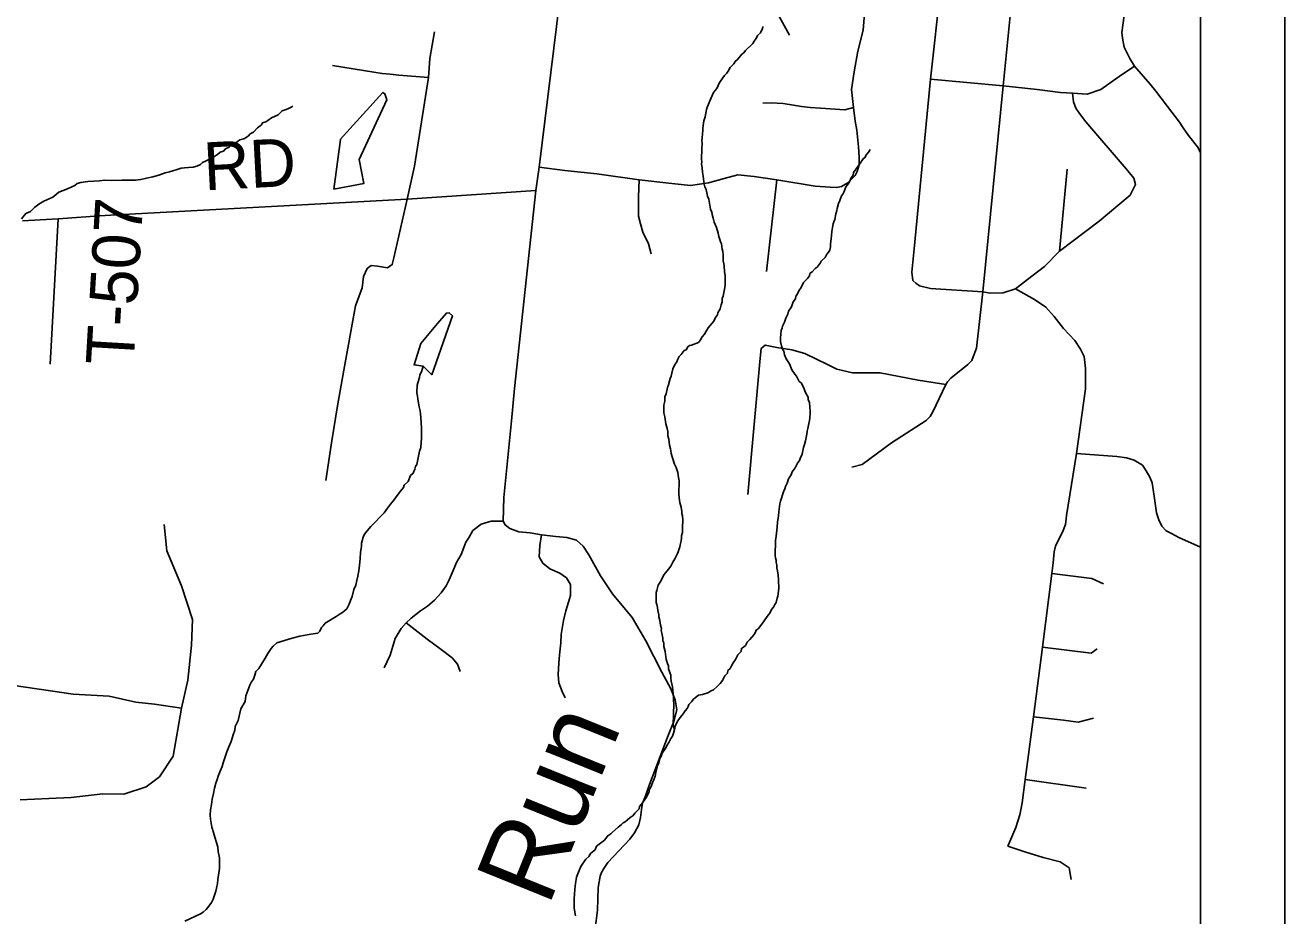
# Model space of a CAD drawing. Extents: x 44.2 to 78.2, y 4.5 to 26.5.
# Drawn here: x 51.74 to 53.236, y 20.407 to 21.465 of the extents above; entities that cross this region are included whole.
import ezdxf

# ---------------------------------------------------------------- set-up
doc = ezdxf.new("R2010")
doc.units = 0
for name, color, linetype in [('GM_X_County_Road', 7, 'Continuous'), ('GM_X_Minor_Lake', 7, 'Continuous'), ('GM_X_Minor_River', 7, 'Continuous'), ('GM_X_Minor_River_Text', 7, 'Continuous'), ('GM_X_Rail_Line', 7, 'Continuous'), ('GM_X_Township_Road', 7, 'Continuous'), ('GM_X_Township_Road_Text', 7, 'Continuous'), ('SH_Cut_Line', 7, 'Continuous'), ('SH_Data', 7, 'Continuous')]:
    doc.layers.add(name, color=color, linetype=linetype)

msp = doc.modelspace()

# ---------------------------------------------------------------- linework, layer by layer
at = {"layer": 'GM_X_County_Road'}
msp.add_lwpolyline([(52.4171, 20.3916), (52.4198, 20.4137), (52.4207, 20.4404), (52.4229, 20.454), (52.4245, 20.4585), (52.4273, 20.4633), (52.432, 20.4704), (52.4582, 20.498), (52.4639, 20.5053), (52.4691, 20.5151), (52.4711, 20.5235), (52.472, 20.5332), (52.4735, 20.5407), (52.4763, 20.5481), (52.4817, 20.5627), (52.5039, 20.621), (52.5106, 20.6377), (52.514, 20.6516), (52.5119, 20.6635), (52.507, 20.6764), (52.4963, 20.6964), (52.4771, 20.7336), (52.4612, 20.7614), (52.4377, 20.7893), (52.4236, 20.8106), (52.4096, 20.8355), (52.4027, 20.8461), (52.3948, 20.8532), (52.3835, 20.8561), (52.3704, 20.8575), (52.3532, 20.8594), (52.34, 20.8616), (52.3266, 20.8631), (52.3159, 20.8668), (52.3104, 20.8711), (52.3079, 20.8757), (52.3085, 20.9039), (52.3176, 20.9946), (52.3212, 21.0331), (52.3467, 21.2684), (52.3505, 21.2962), (52.3746, 21.4919)], dxfattribs=at)
at = {"layer": 'GM_X_Minor_Lake'}
for points in [[(52.1067, 21.2699), (52.1425, 21.2768), (52.137, 21.305), (52.1696, 21.376), (52.1675, 21.3833), (52.1652, 21.3848), (52.1144, 21.3289)], [(52.1146, 21.3291), (52.1067, 21.2699)], [(52.213, 21.0598), (52.2231, 21.0495), (52.2477, 21.1196), (52.2439, 21.1231), (52.2405, 21.1228), (52.23, 21.1105)], [(52.23, 21.1105), (52.2102, 21.0866), (52.2021, 21.0613), (52.213, 21.0598)]]:
    msp.add_lwpolyline(points, dxfattribs=at)
at = {"layer": 'GM_X_Minor_River'}
for points in [[(52.5227, 21.0782), (52.525, 21.0793), (52.527, 21.0827), (52.5293, 21.0841), (52.5316, 21.0848), (52.5396, 21.088), (52.542, 21.091), (52.544, 21.0944), (52.5471, 21.0977), (52.5511, 21.1052), (52.5535, 21.1082), (52.5558, 21.1104), (52.5581, 21.113), (52.5601, 21.1175), (52.5625, 21.1208), (52.5629, 21.1231), (52.5654, 21.128), (52.5666, 21.1325), (52.5678, 21.1362), (52.5679, 21.14), (52.5691, 21.1427), (52.5701, 21.1491), (52.5709, 21.1532), (52.5714, 21.1559), (52.5716, 21.1631), (52.5713, 21.1673), (52.5706, 21.1718), (52.5701, 21.1791), (52.5697, 21.1813), (52.5691, 21.1848), (52.5689, 21.192), (52.5686, 21.1958), (52.5679, 21.1985), (52.5669, 21.2049), (52.5658, 21.2072), (52.5652, 21.2103), (52.5641, 21.2137), (52.5631, 21.2176), (52.5613, 21.2244), (52.5585, 21.2309), (52.5571, 21.2355), (52.556, 21.2397), (52.5557, 21.2428), (52.5539, 21.2462), (52.553, 21.2535), (52.5519, 21.2581), (52.5505, 21.2615), (52.5488, 21.2695), (52.5474, 21.2726), (52.5467, 21.276), (52.5457, 21.2821), (52.5454, 21.2855), (52.5444, 21.2901), (52.5442, 21.2954), (52.5435, 21.2996), (52.5436, 21.3023), (52.5433, 21.3057), (52.5436, 21.3178), (52.5441, 21.3243), (52.5438, 21.3281), (52.5443, 21.3303), (52.5444, 21.3364), (52.5449, 21.339), (52.545, 21.3425), (52.5459, 21.3485), (52.5463, 21.3511), (52.5476, 21.3557), (52.5493, 21.3647), (52.5506, 21.3681), (52.5538, 21.3756), (52.5574, 21.3846), (52.5614, 21.3894), (52.5633, 21.3932), (52.5642, 21.3958), (52.5661, 21.3981), (52.5705, 21.4051), (52.5736, 21.4077), (52.5752, 21.41), (52.5772, 21.4145), (52.5799, 21.4167), (52.5819, 21.4189), (52.5834, 21.4215), (52.5858, 21.4237), (52.5881, 21.4263), (52.5913, 21.4304), (52.5936, 21.4319), (52.5955, 21.4348), (52.6041, 21.443), (52.6057, 21.4459), (52.6084, 21.4489), (52.61, 21.4523), (52.6132, 21.4556), (52.6144, 21.4582), (52.6156, 21.4605), (52.616, 21.4631)], [(51.7359, 21.2346), (51.741, 21.241), (51.7467, 21.2435), (51.7518, 21.2486), (51.7565, 21.2523), (51.7626, 21.2556), (51.7734, 21.2606), (51.7804, 21.2665), (51.7907, 21.2704), (51.7957, 21.2729), (51.7992, 21.2743), (51.8023, 21.2765), (51.8065, 21.2779), (51.8149, 21.2792), (51.8221, 21.2794), (51.8286, 21.28), (51.8347, 21.2806), (51.8426, 21.2804), (51.8552, 21.2805), (51.8631, 21.2806), (51.8715, 21.2808), (51.8776, 21.2814), (51.8845, 21.2831), (51.8921, 21.2844), (51.899, 21.2865), (51.9024, 21.2876), (51.9067, 21.2894), (51.9116, 21.2907), (51.9158, 21.2918), (51.9208, 21.2935), (51.9258, 21.2949), (51.9296, 21.2952), (51.9342, 21.2955), (51.9399, 21.2961), (51.9441, 21.2971), (51.9487, 21.2993), (51.951, 21.3015), (51.9553, 21.3036), (51.9607, 21.3065), (51.9634, 21.308), (51.9688, 21.3113), (51.9719, 21.3138), (51.9757, 21.3152), (51.9784, 21.3178), (51.9827, 21.32), (51.9861, 21.3229), (51.9908, 21.3255), (51.9954, 21.3284), (52, 21.3298), (52.0027, 21.3312), (52.0054, 21.3331), (52.0077, 21.3357), (52.0116, 21.3378), (52.0163, 21.3426), (52.0209, 21.3463), (52.0221, 21.3486), (52.026, 21.35), (52.0283, 21.3514), (52.0329, 21.3547), (52.0406, 21.3583), (52.0457, 21.3631), (52.0503, 21.3645), (52.0529, 21.3656), (52.056, 21.3674), (52.0583, 21.3685)], [(52.6853, 21.1844), (52.69, 21.1888), (52.692, 21.1929), (52.6943, 21.1951), (52.6959, 21.1974), (52.6964, 21.2015), (52.6964, 21.205), (52.6974, 21.211), (52.6978, 21.2148), (52.698, 21.2197), (52.6988, 21.2246), (52.6997, 21.2288), (52.7005, 21.231), (52.7017, 21.234), (52.7027, 21.2405), (52.7039, 21.2446), (52.7043, 21.2469), (52.706, 21.2529), (52.7076, 21.2563), (52.7097, 21.2619), (52.7112, 21.2641), (52.7128, 21.2671), (52.7149, 21.2728), (52.7165, 21.275), (52.7192, 21.2787), (52.7212, 21.2836), (52.7236, 21.2866), (52.724, 21.2896), (52.7288, 21.2967), (52.7311, 21.2996), (52.7351, 21.306), (52.7374, 21.3074), (52.7394, 21.3112), (52.7421, 21.3142), (52.7434, 21.3172)], [(52.6108, 20.7478), (52.6127, 20.75), (52.6147, 20.753), (52.617, 20.7559), (52.6186, 20.7586), (52.6206, 20.7612), (52.6226, 20.7641), (52.6245, 20.7664), (52.6265, 20.7709), (52.6289, 20.7735), (52.6305, 20.7765), (52.6321, 20.7791), (52.6333, 20.784), (52.6338, 20.7866), (52.6351, 20.7957), (52.6352, 20.7995), (52.6349, 20.8018), (52.6347, 20.8059), (52.6344, 20.8116), (52.6334, 20.8166), (52.6327, 20.8204), (52.6328, 20.8234), (52.6321, 20.8265), (52.6318, 20.8292), (52.6311, 20.8318), (52.6308, 20.8349), (52.6313, 20.8527), (52.6318, 20.858), (52.6332, 20.8686), (52.6337, 20.8743), (52.6347, 20.8818), (52.6352, 20.8867), (52.6362, 20.8962), (52.637, 20.8992), (52.6407, 20.9105), (52.6423, 20.9142), (52.6432, 20.9169), (52.6452, 20.9206), (52.6468, 20.9259), (52.65, 20.9307), (52.6508, 20.9341), (52.6547, 20.939), (52.6572, 20.9446), (52.6595, 20.9476), (52.6603, 20.9502), (52.6628, 20.9554), (52.6645, 20.963), (52.6657, 20.9667), (52.6669, 20.9709), (52.6683, 20.9788), (52.6688, 20.9826), (52.6696, 20.9856), (52.6709, 20.9917), (52.6714, 20.9951), (52.6718, 20.9981), (52.6724, 21.0041), (52.6724, 21.0064), (52.6721, 21.011), (52.6715, 21.0167), (52.6701, 21.0201), (52.6698, 21.0228), (52.6673, 21.0278), (52.6662, 21.0305), (52.6644, 21.0347), (52.6615, 21.0401), (52.6593, 21.0417), (52.656, 21.0478), (52.6542, 21.0501), (52.6505, 21.0552), (52.648, 21.0624), (52.644, 21.0686), (52.6418, 21.0732), (52.6412, 21.0774), (52.6397, 21.0801), (52.6383, 21.0839), (52.6373, 21.0889), (52.637, 21.0931), (52.6375, 21.098), (52.638, 21.1022), (52.6392, 21.1048), (52.6397, 21.1074), (52.642, 21.1119), (52.6433, 21.1168), (52.6457, 21.1213), (52.6466, 21.1251), (52.6501, 21.1303), (52.6522, 21.1363), (52.6549, 21.1397), (52.6554, 21.1427), (52.6569, 21.1449), (52.6593, 21.1498), (52.6613, 21.1524), (52.6645, 21.1591), (52.6692, 21.1639), (52.6715, 21.1669), (52.672, 21.1696), (52.6747, 21.1718), (52.6782, 21.1758), (52.6805, 21.1773), (52.6841, 21.1821), (52.6853, 21.1844)], [(52.5112, 20.6278), (52.5106, 20.6305), (52.5099, 20.6339), (52.5105, 20.6586), (52.5102, 20.6628), (52.5103, 20.6665), (52.5097, 20.6704), (52.5091, 20.6787), (52.5074, 20.6856), (52.5071, 20.6894), (52.5068, 20.6928), (52.5058, 20.6959), (52.5043, 20.7001), (52.5041, 20.7039), (52.503, 20.7066), (52.5016, 20.7112), (52.5003, 20.7207), (52.4986, 20.7268), (52.4987, 20.731), (52.4976, 20.7337), (52.4973, 20.7367), (52.4963, 20.7428), (52.4956, 20.7458), (52.4957, 20.7481), (52.4947, 20.7523), (52.494, 20.7576), (52.4926, 20.7619), (52.4927, 20.7645), (52.4917, 20.7695), (52.491, 20.7729), (52.4903, 20.7767), (52.4896, 20.779), (52.4897, 20.7813), (52.4895, 20.7874), (52.4896, 20.7911), (52.4904, 20.7934), (52.4921, 20.7998), (52.4944, 20.8032), (52.4972, 20.8084), (52.4988, 20.8118), (52.5008, 20.8144), (52.5043, 20.8188), (52.5071, 20.8222), (52.5095, 20.827), (52.5118, 20.8308), (52.5134, 20.8342), (52.515, 20.8371), (52.5155, 20.8394), (52.5175, 20.8451), (52.5184, 20.8492), (52.5192, 20.8522), (52.5197, 20.856), (52.5198, 20.8583), (52.5206, 20.862), (52.5208, 20.8677), (52.5209, 20.8715), (52.5213, 20.8738), (52.521, 20.8776), (52.5207, 20.8821), (52.5201, 20.8848), (52.5201, 20.8871), (52.5191, 20.8924), (52.5177, 20.8978), (52.5174, 20.9001), (52.5165, 20.9077), (52.5169, 20.9236), (52.5162, 20.9274), (52.5152, 20.9335), (52.5142, 20.9369), (52.5131, 20.9393), (52.5113, 20.9435), (52.5088, 20.9507), (52.5074, 20.9561), (52.5071, 20.9591), (52.5064, 20.9614), (52.5054, 20.966), (52.5044, 20.9732), (52.5034, 20.9771), (52.5035, 20.982), (52.5025, 20.9858), (52.5011, 20.9912), (52.4998, 20.9995), (52.4988, 21.0041), (52.4988, 21.0064), (52.4985, 21.0094), (52.4986, 21.0136), (52.4999, 21.0181), (52.5, 21.0234), (52.5013, 21.0268), (52.503, 21.0344), (52.5042, 21.0374), (52.5063, 21.0449), (52.5075, 21.0479), (52.508, 21.0513), (52.5092, 21.0566), (52.5116, 21.0618), (52.5136, 21.0641), (52.5152, 21.0682), (52.5168, 21.0712), (52.5191, 21.0734), (52.5227, 21.0782)], [(52.2086, 20.9586), (52.2102, 20.9631), (52.2109, 20.9745), (52.211, 20.9802), (52.2108, 20.9862), (52.2106, 20.9927), (52.2097, 21.0037), (52.2091, 21.0083), (52.208, 21.0114), (52.2071, 21.0182), (52.2067, 21.0209), (52.2061, 21.0239), (52.2054, 21.0281), (52.2056, 21.0372), (52.2065, 21.0398), (52.2085, 21.0462), (52.209, 21.0496), (52.211, 21.053), (52.2122, 21.0568), (52.213, 21.0598)], [(51.9666, 20.4361), (51.9675, 20.4398), (51.9688, 20.4451), (51.9693, 20.45), (51.9711, 20.4633), (51.9713, 20.4682), (51.971, 20.4724), (51.9711, 20.4758), (51.9697, 20.4834), (51.9691, 20.4883), (51.9674, 20.4941), (51.9656, 20.5002), (51.9639, 20.5059), (51.9621, 20.5121), (51.9611, 20.517), (51.9605, 20.5216), (51.9602, 20.5265), (51.9604, 20.5326), (51.9617, 20.539), (51.9626, 20.5454), (51.9639, 20.5522), (51.9652, 20.5586), (51.9669, 20.5643), (51.9685, 20.5688), (51.9697, 20.5729), (51.9718, 20.5786), (51.9742, 20.5842), (51.9755, 20.5887), (51.9775, 20.5947), (51.98, 20.6015), (51.982, 20.6075), (51.9848, 20.6139), (51.9873, 20.6218), (51.9894, 20.6274), (51.9898, 20.6316), (51.9934, 20.6387), (51.9965, 20.6527), (52.0016, 20.6616), (52.0025, 20.6681), (52.0071, 20.6809), (52.0091, 20.685), (52.0114, 20.6879), (52.0131, 20.6928), (52.0143, 20.697), (52.0178, 20.7007), (52.021, 20.7059), (52.0253, 20.713), (52.0285, 20.7186), (52.0325, 20.7242), (52.0348, 20.7272), (52.0391, 20.7312), (52.0575, 20.7368), (52.0663, 20.7389), (52.0796, 20.7416), (52.088, 20.7428), (52.0903, 20.7451), (52.0923, 20.7492), (52.0943, 20.7514), (52.0967, 20.7544), (52.1005, 20.7569), (52.1098, 20.7624), (52.1144, 20.7657), (52.1171, 20.7671), (52.1198, 20.7697), (52.1222, 20.7716), (52.1234, 20.7738), (52.125, 20.7772), (52.1266, 20.7813), (52.1286, 20.7862), (52.1307, 20.7945), (52.1328, 20.7997), (52.134, 20.805), (52.1353, 20.8103), (52.1366, 20.8167), (52.1372, 20.8235), (52.1381, 20.8307), (52.1387, 20.839), (52.1396, 20.8455), (52.1397, 20.8496), (52.1418, 20.8568), (52.1434, 20.8602), (52.1465, 20.8642), (52.1508, 20.8691), (52.1559, 20.8746), (52.1614, 20.8802), (52.1665, 20.8857), (52.1704, 20.8909), (52.1743, 20.8958), (52.1779, 20.9006), (52.1822, 20.9062), (52.1861, 20.9114), (52.1896, 20.9155), (52.1905, 20.9185), (52.1951, 20.9229), (52.198, 20.9297), (52.2011, 20.9326), (52.2031, 20.9375), (52.2039, 20.9405), (52.2055, 20.9431), (52.2073, 20.9529), (52.2086, 20.9586)], [(52.3936, 20.4067), (52.3929, 20.4112), (52.3923, 20.4162), (52.392, 20.42), (52.3922, 20.4272), (52.3927, 20.4325), (52.3929, 20.4382), (52.3933, 20.442), (52.3938, 20.4454), (52.3947, 20.4499), (52.3951, 20.4529), (52.3964, 20.4567), (52.398, 20.4608), (52.4, 20.4653), (52.4032, 20.4702), (52.4059, 20.4743), (52.4094, 20.4772), (52.4118, 20.4813), (52.4172, 20.4853), (52.4185, 20.4895), (52.4281, 20.4968), (52.4321, 20.502), (52.4356, 20.5042), (52.4375, 20.5064), (52.4445, 20.5123), (52.4484, 20.5153), (52.4503, 20.5175), (52.4526, 20.5186), (52.4553, 20.5208), (52.4588, 20.5237), (52.4623, 20.5259), (52.4643, 20.5289), (52.4694, 20.5341), (52.4698, 20.5367), (52.4722, 20.5397), (52.4761, 20.5449), (52.4781, 20.5479), (52.4797, 20.5512), (52.4813, 20.5542), (52.4813, 20.5565), (52.4829, 20.5588), (52.4841, 20.5618), (52.4854, 20.5659), (52.487, 20.5696), (52.4882, 20.5727), (52.4891, 20.5772), (52.4903, 20.5817), (52.4912, 20.5851), (52.4928, 20.5888), (52.494, 20.5937), (52.496, 20.5971), (52.4965, 20.6001), (52.5004, 20.6053), (52.5024, 20.6095), (52.5044, 20.6128), (52.5068, 20.6177), (52.5088, 20.6203), (52.5096, 20.6226), (52.5112, 20.6278), (52.5121, 20.6323), (52.5145, 20.6372), (52.5181, 20.6424), (52.5216, 20.6469), (52.524, 20.6503), (52.5263, 20.6532), (52.5275, 20.6555), (52.5283, 20.6577), (52.5315, 20.6611), (52.5334, 20.664), (52.5361, 20.6662), (52.5396, 20.6688), (52.5423, 20.6695), (52.5446, 20.6698), (52.5507, 20.6719), (52.555, 20.6741), (52.5576, 20.6752), (52.5619, 20.6792), (52.5654, 20.6829), (52.5682, 20.6863), (52.571, 20.6919), (52.5741, 20.6952), (52.5746, 20.6982), (52.5773, 20.7008), (52.5789, 20.7038), (52.5809, 20.7072), (52.5836, 20.7113), (52.5864, 20.7169), (52.5903, 20.721), (52.5908, 20.7244), (52.5931, 20.7258), (52.5955, 20.7281), (52.5974, 20.7318), (52.6006, 20.7351), (52.606, 20.7411), (52.6076, 20.7437), (52.6084, 20.7463), (52.6108, 20.7478)], [(51.93, 20.4006), (51.9485, 20.4092), (51.9516, 20.4114), (51.9551, 20.4144), (51.9586, 20.4184), (51.9618, 20.4229), (51.9637, 20.4266), (51.9642, 20.4289), (51.9666, 20.4361)]]:
    msp.add_lwpolyline(points, dxfattribs=at)
at = {"layer": 'GM_X_Rail_Line'}
msp.add_lwpolyline([(53.1359, 18.9756), (53.1359, 25.4014)], dxfattribs=at)
at = {"layer": 'GM_X_Township_Road'}
for p, q in [((52.6353, 21.476), (52.6478, 21.4527)), ((52.6207, 21.1722), (52.6329, 21.281)), ((52.9682, 21.1965), (52.9773, 21.2937)), ((51.7794, 21.2349), (51.77, 21.0621)), ((52.9278, 20.5687), (53, 20.5585))]:
    msp.add_line(p, q, dxfattribs=at)
for points in [[(52.9178, 21.7737), (52.9016, 21.6405), (52.9013, 21.6312), (52.9016, 21.6247), (52.9035, 21.6184), (52.9073, 21.6033), (52.9133, 21.5839), (52.9147, 21.5773), (52.9169, 21.5689), (52.918, 21.5601), (52.9172, 21.5503), (52.9161, 21.5366), (52.9128, 21.5079), (52.9016, 21.3926), (52.8772, 21.1481)], [(52.8275, 21.5118), (52.8154, 21.4006), (52.7959, 21.1991), (52.7929, 21.1712), (52.7944, 21.1613), (52.7977, 21.1583), (52.8022, 21.1553), (52.8151, 21.152), (52.8772, 21.1481), (52.8859, 21.1463), (52.9015, 21.147), (52.9161, 21.1516), (52.9305, 21.1626), (52.9505, 21.1781), (52.9682, 21.1965), (53.0156, 21.232), (53.0521, 21.2627), (53.0587, 21.2756), (53.0565, 21.2831), (53.0477, 21.294), (52.9997, 21.3498), (52.992, 21.3599), (52.9879, 21.3662), (52.9851, 21.3737), (52.984, 21.3838)], [(52.3505, 21.2962), (52.3811, 21.292), (52.419, 21.2882), (52.4694, 21.281), (52.5081, 21.2768), (52.5304, 21.2743), (52.5518, 21.2773), (52.5703, 21.2827), (52.5863, 21.2869), (52.606, 21.2848), (52.6329, 21.281), (52.6784, 21.2735), (52.6961, 21.2722), (52.7037, 21.2718), (52.7094, 21.2732), (52.717, 21.2773), (52.722, 21.2822), (52.7257, 21.2861), (52.7283, 21.2911), (52.7306, 21.2989), (52.7307, 21.3078), (52.7297, 21.3202), (52.7276, 21.3401), (52.7257, 21.3507), (52.7238, 21.3669), (52.7214, 21.3884), (52.7247, 21.4094), (52.7291, 21.434), (52.7351, 21.4589), (52.7375, 21.4886)], [(53.045, 21.4761), (53.0425, 21.456), (53.043, 21.4494), (53.0452, 21.4387), (53.0518, 21.425), (53.0573, 21.4162), (53.076, 21.3948), (53.0826, 21.3863), (53.0966, 21.3682), (53.1109, 21.3495), (53.1152, 21.3429), (53.1216, 21.3336), (53.1323, 21.3201), (53.1359, 21.3133)], [(52.1938, 21.2579), (52.2025, 21.2971), (52.2191, 21.4025), (52.2208, 21.4251), (52.2262, 21.457)], [(52.2191, 21.4025), (52.1841, 21.4054), (52.1737, 21.4067), (52.1642, 21.4073), (52.1542, 21.409), (52.1052, 21.4168)], [(52.8154, 21.4006), (52.9016, 21.3926), (52.942, 21.3882), (52.9695, 21.3846), (52.984, 21.3838), (53.0014, 21.3828), (53.0175, 21.3882), (53.0392, 21.4036), (53.0573, 21.4162)], [(52.616, 21.3721), (52.6261, 21.3723), (52.6403, 21.3716), (52.6525, 21.3696), (52.6622, 21.368), (52.6722, 21.3668), (52.6847, 21.366), (52.7137, 21.3643), (52.7238, 21.3669)], [(52.4837, 21.1932), (52.4803, 21.205), (52.4736, 21.2188), (52.4711, 21.2289), (52.4686, 21.2377), (52.4686, 21.2609), (52.4694, 21.281)], [(51.8285, 21.2382), (51.8423, 21.2391), (52.1938, 21.2579), (52.3467, 21.2684)], [(52.1938, 21.2579), (52.1781, 21.1884), (52.1762, 21.1804), (52.1707, 21.1766), (52.1586, 21.1785), (52.151, 21.1794), (52.1465, 21.1759), (52.1421, 21.1663), (52.1404, 21.1529), (52.1324, 21.1314), (52.1187, 21.0551), (52.1114, 21.0128), (52.1041, 20.9687), (52.0973, 20.9238)], [(51.7371, 21.2322), (51.7794, 21.2349), (51.8285, 21.2382)], [(52.8772, 21.1481), (52.87, 21.0811), (52.8645, 21.0675), (52.8641, 21.0664), (52.8595, 21.0619), (52.8393, 21.0453), (52.8355, 21.0412), (52.8336, 21.0378), (52.8178, 21.0053), (52.8148, 21), (52.8102, 20.9951), (52.7691, 20.9688), (52.7341, 20.9429), (52.722, 20.9396)], [(52.9161, 21.1516), (52.9262, 21.1459), (52.9388, 21.139), (52.952, 21.1297), (52.9622, 21.1186), (52.9733, 21.1045), (52.9865, 21.0904), (52.9934, 21.0799), (52.9976, 21.0712), (52.9994, 21.0571), (52.9991, 21.0328), (52.9886, 20.9559), (52.9768, 20.8825), (52.9764, 20.8785)], [(52.5983, 20.9073), (52.613, 21.0694), (52.6142, 21.0808), (52.619, 21.0847), (52.6329, 21.082), (52.6506, 21.0793), (52.6662, 21.0748), (52.6806, 21.0676), (52.692, 21.0622), (52.704, 21.0562), (52.7226, 21.052), (52.7553, 21.052), (52.8004, 21.043), (52.8336, 21.0378)], [(52.9886, 20.9559), (53.0364, 20.9523), (53.0479, 20.951), (53.0572, 20.948), (53.0668, 20.9422), (53.0714, 20.9354), (53.0758, 20.928), (53.0783, 20.9212), (53.0807, 20.9053), (53.0837, 20.8856), (53.0862, 20.8771), (53.09, 20.8695), (53.0952, 20.8643), (53.1013, 20.861), (53.11, 20.8563), (53.1359, 20.8448)], [(52.9764, 20.8785), (52.9756, 20.8715), (52.9718, 20.8625), (52.9668, 20.8526), (52.9637, 20.8458), (52.9621, 20.8394), (52.9609, 20.8262), (52.9592, 20.8134), (52.948, 20.7259), (52.9374, 20.6434), (52.9278, 20.5687), (52.9242, 20.541), (52.9224, 20.5326)], [(51.7345, 20.5445), (51.7684, 20.5463), (51.7951, 20.5475), (51.8326, 20.5518), (51.8577, 20.5514), (51.8841, 20.5602), (51.9, 20.5721), (51.9162, 20.5967), (51.9259, 20.6535), (51.9334, 20.6866), (51.9378, 20.7284), (51.9389, 20.7589), (51.9259, 20.799), (51.9085, 20.8402), (51.9053, 20.8717)], [(52.1665, 20.7015), (52.1738, 20.7166), (52.1798, 20.7363), (52.1869, 20.7483), (52.1927, 20.7549), (52.1988, 20.7603), (52.2099, 20.7692), (52.2179, 20.7748), (52.2262, 20.7817), (52.2342, 20.7904), (52.2401, 20.7987), (52.2436, 20.8059), (52.2472, 20.8143), (52.2525, 20.8264), (52.2579, 20.836), (52.2613, 20.8443), (52.2637, 20.8506), (52.2675, 20.8567), (52.272, 20.8644), (52.2817, 20.8719), (52.2937, 20.8756), (52.3079, 20.8757)], [(52.3813, 20.6657), (52.3778, 20.6734), (52.3741, 20.6835), (52.3731, 20.6935), (52.3738, 20.7071), (52.3746, 20.717), (52.3763, 20.7311), (52.3768, 20.7411), (52.3795, 20.7576), (52.3824, 20.769), (52.3855, 20.7795), (52.388, 20.7875), (52.388, 20.8003), (52.3831, 20.8082), (52.3751, 20.8137), (52.3634, 20.8191), (52.3549, 20.8256), (52.3508, 20.8333), (52.3513, 20.8469), (52.3532, 20.8594)], [(52.9592, 20.8134), (53.0069, 20.8074), (53.0208, 20.8011)], [(52.1927, 20.7549), (52.2178, 20.7355), (52.2343, 20.7231), (52.2474, 20.7132), (52.2537, 20.7056), (52.257, 20.6971)], [(52.948, 20.7259), (53.0061, 20.7187), (53.0129, 20.724)], [(51.3873, 20.6565), (51.4119, 20.6644), (51.4758, 20.6854), (51.543, 20.6961), (51.615, 20.6991), (51.7137, 20.6825), (51.7975, 20.67), (51.8403, 20.6676), (51.8718, 20.6605), (51.8938, 20.6581), (51.9259, 20.6535)], [(52.9374, 20.6434), (52.9731, 20.6391), (52.9906, 20.6369), (53.0086, 20.6416)], [(52.9224, 20.5326), (52.9212, 20.527), (52.9164, 20.5117), (52.907, 20.4897)], [(52.907, 20.4897), (52.9274, 20.483), (52.949, 20.4762), (52.9692, 20.4712), (52.9799, 20.4638), (52.9824, 20.4502)]]:
    msp.add_lwpolyline(points, dxfattribs=at)
at = {"layer": 'SH_Cut_Line'}
msp.add_lwpolyline([(48.642, 18.6014), (53.1359, 18.6014), (53.1359, 25.4014)], dxfattribs=at)
at = {"layer": 'SH_Data'}
for p, q in [((53.2359, 25.5014), (53.2359, 18.5014)), ((53.1359, 25.4014), (53.1359, 18.6014))]:
    msp.add_line(p, q, dxfattribs=at)

# ---------------------------------------------------------------- texts
at = {"layer": 'GM_X_Minor_River_Text'}
msp.add_text('Run', height=0.09471, rotation=67.9505, dxfattribs=at).set_placement((52.3614, 20.4165))
at = {"layer": 'GM_X_Township_Road_Text'}
for s, rotation, p in [('RD', 2.9612, (51.9535, 21.2685)), ('T-507', 86.6333, (51.869, 21.0596))]:
    msp.add_text(s, height=0.05682, rotation=rotation, dxfattribs=at).set_placement(p)

doc.saveas('drawing.dxf')
